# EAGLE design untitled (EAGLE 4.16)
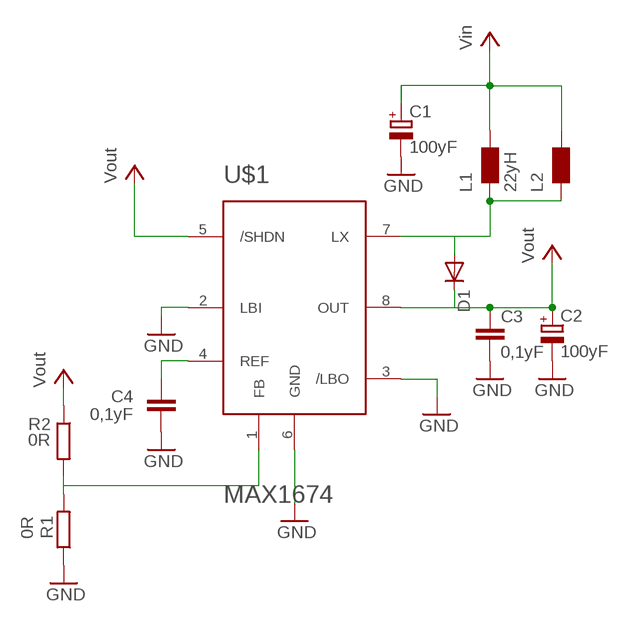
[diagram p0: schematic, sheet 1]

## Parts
C1  100yF  CPOL-EUSANYO_SMD_C6  [SANYO-OSCON_SMD_C6]
C2  100yF  CPOL-EUSANYO_SMD_C6  [SANYO-OSCON_SMD_C6]
C3  0,1yF  C-EUC0603  [C0603]
C4  0,1yF  C-EUC0603  [C0603]
D1  DIODE-SOD123  [SOD123]
L1  22yH  WE-PD_L/XL/XXL  [WE-PD_L/XL/XXL]
L2  WE-PD_S/M  [WE-PD_S/M]
R1  0R  R-EU_R0603  [R0603]
R2  0R  R-EU_R0603  [R0603]
U$1  MAX1674  [UMAX8]

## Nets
ACK: R1.2 R2.2 U$1.1(FB)
GND: C1.- C2.- C3.2 C4.1 R1.1 U$1.2(LBI) U$1.3(/LBO) U$1.6(GND)
N$2: D1.A L1.2 L2.2 U$1.7(LX)
N$3: C4.2 U$1.4(REF)
VIN: C1.+ L1.1 L2.1 ; supply symbol labelled Vin
VOUT: C2.+ C3.1 D1.C R2.1 U$1.5(/SHDN) U$1.8(OUT) ; supply symbol labelled Vout

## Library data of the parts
C1 C2 = rcl:CPOL-EU: POLARIZED CAPACITOR, European symbol
C3 C4 = rcl:C-EU: CAPACITOR, European symbol
D1 = diode:DIODE-: DIODE
L1 L2 = wuerth-elektronik:WE-PD: SMD-Shielded Power Inductors WE-PD
R1 R2 = rcl:R-EU_: RESISTOR, European symbol
U$1 = max167x:MAX1674

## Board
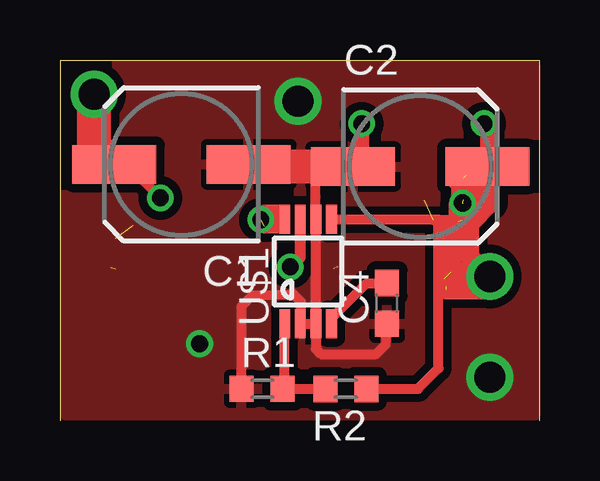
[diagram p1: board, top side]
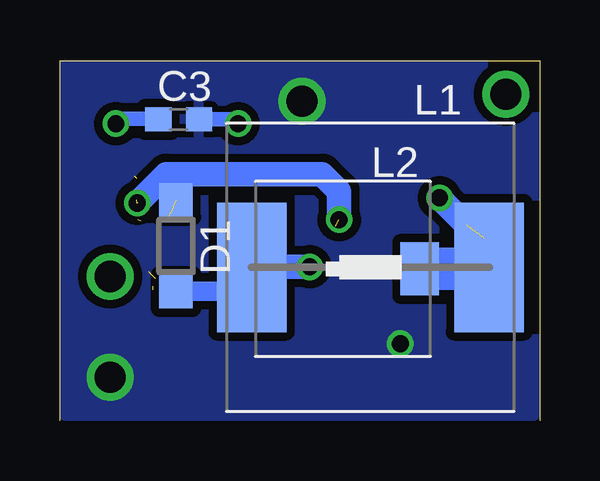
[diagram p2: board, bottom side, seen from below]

Size 20 x 15 mm. Coordinates in mm from the lower left corner, seen from the top.
Outline: 20,0 20,15 0,15 0,0
Copper layers (1*16): Top 0.035mm / dielectric 1.5mm / Bottom 0.035mm
Design rules "default": minimum track width 10mil, minimum drill 24mil, track to track 8mil, track to pad 8mil, pad to pad 8mil, via to via 8mil, smd to smd 8mil, copper to edge 0mil, drill to drill 8mil, minimum pad ring 10mil, minimum via ring 8mil, stop-mask expansion 4mil, vias tented up to drill 0mil, thermal gap 10mil

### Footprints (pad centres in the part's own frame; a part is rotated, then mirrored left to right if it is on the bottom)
SANYO-OSCON_SMD_C6 = smd 3.5 x 1.6: + 2.8,0; - -2.8,0
C0603 = smd 1.1 x 1: 1 -0.85,0; 2 0.85,0
SOD123 = smd 1.4 x 1.4: A 1.9,0; C -1.9,0
WE-PD_L/XL/XXL = smd 2.9 x 5.4: 1 -4.95,0; 2 4.95,0
WE-PD_S/M = smd 1.6 x 2.2: 1 -3.2,0; 2 3.2,0
R0603 = smd 1 x 1.1: 1 -0.85,0; 2 0.85,0
UMAX8 = smd 0.45 x 1.2: 1 -0.975,-2.175; 2 -0.325,-2.175; 3 0.325,-2.175; 4 0.975,-2.175; 5 0.975,2.175; 6 0.325,2.175; 7 -0.325,2.175; 8 -0.975,2.175

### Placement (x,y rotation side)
C1  5.05,10.69 180 top
C2  15.01,10.6 0 top
C3  15.05,12.55 0 bottom
C4  13.62,4.89 90 top
D1  15.16,7.29 270 bottom
L1  7.05,6.39 180 bottom
L2  8.2,6.33 180 bottom
R1  8.42,1.34 0 top
R2  11.91,1.33 180 top
U$1  10.33,6.22 0 top

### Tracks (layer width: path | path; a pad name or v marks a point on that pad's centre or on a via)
ACK
  Top 0.406: U$1.1 9.36,1.47 9.27,1.38 R1.2 9.27,1.48 9.37,1.58 9.62,1.33 R2.2
GND  (via drill 0.7, 1.3)
  Top 0.406: C1.- 7.86,10.6 7.86,10.56 | U$1.2 10.04,4.05 10.05,4.04 10.05,4.05 U$1.3 10.66,4.17 10.67,4.18 10.66,4.19 | 12.57,10.88 12.27,10.58 12.25,10.6 C2.- 10.65,10.6 U$1.6 10.66,4.19 | U$1.2 | U$1.2 | U$1.2 10.01,4.06 | R1.1 7.57,4.78 8.02,5.22 9.72,5.28 10.02,4.98 10.02,4.18 10.01,4.17 U$1.2 | U$1.2 10.01,4.24 | 10.66,4.19 10.66,2.99 10.87,2.78 13.17,2.78 13.57,3.18 13.57,3.88 13.67,3.98 13.62,4.03 C4.1
  Top 0.61: 12.57,10.88 v12.57,12.38
  Top 1.422: 10.65,10.6 7.86,10.6
  Bottom 0.406: v12.57,12.38 12.75,12.56
  Bottom 0.61: 12.75,12.56 C3.2
  other vias: 5.81,3.21 9.91,13.31 17.91,1.81
  pour Top (isolate 0.35): 0.21,14.81 19.81,14.81 19.81,0.21 0.21,0.21
  pour Bottom (isolate 0.35): 0.21,14.81 19.81,14.81 19.81,0.21 0.21,0.21
N$2  (via drill 0.7)  (1 unrouted)
  Top 0.406: U$1.7 10.01,8.44 10.01,8.64 10.02,8.72 | 9.61,6.41 9.6,6.42 v9.58,6.42
  Top 0.45: v9.58,6.42 v9.59,6.42 9.6,6.4 10.01,6.81 10.01,8.64
  Bottom 0.406: L1.2 11.98,6.39 11.97,6.38 11.57,6.42
  Bottom 0.813: L1.2 11.99,6.39 11.91,6.31 12.83,5.39 D1.A
  Bottom 1.016: v9.58,6.42 11.57,6.42
N$3
  Top 0.406: U$1.4 11.31,4.08 11.29,4.1 11.31,4.12 11.31,4.27 12.77,5.73 C4.2
N$4  (via drill 0.7)
  other vias: 4.17,9.29
N$8  (via drill 0.7)
  other vias: 12.57,12.38
N$9  (via drill 0.7)
  other vias: 17.67,12.38
VIN  (via drill 0.7, 1.3)  (2 unrouted)
  Top 0.406: C1.+ 2.77,10.69 v4.17,9.29
  Top 1.422: C1.+ 2.25,10.66 2.21,10.61 1.41,11.41 v1.41,13.61
  Bottom 1.016: v4.17,9.29 3.03,8.15
  Bottom 1.778: L2.1 2.31,6.33 2.31,7.61
VOUT  (via drill 0.7, 1.3)  (8 unrouted)
  Top 0.406: U$1.5 11.33,8.38 15.53,8.38 | 15.55,8.38 15.53,8.38 | 15.77,8.38 16.77,8.38 | 15.77,8.38 15.55,8.38 | 16.77,8.38 17.07,8.38 | 15.55,8.38 15.54,8.37 15.53,8.38 | U$1.8 8.38,8.4 v8.36,8.38 | 16.77,8.38 v16.77,9.08 | R2.1 14.92,1.33 15.77,2.18 15.77,8.38
  Top 0.61: C2.+ 17.81,12.24 v17.67,12.38 | 9.21,8.71 8.51,8.71 8.51,8.11 9.21,8.11
  Top 0.813: 16.61,8.31 16.61,9.01 | 16.31,8.11 16.31,6.21 17.26,6.21 17.48,6.44 | 16.01,5.91 16.01,5.71 16.11,5.61 | 17.07,8.38 17.06,8.37 17.06,6.86 17.48,6.44 | 17.48,6.44 v17.91,6.01 | 17.96,5.51 17.91,5.46 16.11,5.46
  Top 1.016: C2.+ 17.81,9.12 17.07,8.38 | 16.61,10.11 16.81,10.11 16.81,9.21 | 16.91,9.51 16.91,10.21
  Bottom 0.406: 15.92,12.58 C3.1
  Bottom 0.61: v17.67,12.38 17.47,12.58 15.92,12.58
  Bottom 1.016: v8.36,8.38 8.36,9.57 9.07,10.28 15.57,10.28 v16.77,9.08
  other vias: 16.78,9.07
